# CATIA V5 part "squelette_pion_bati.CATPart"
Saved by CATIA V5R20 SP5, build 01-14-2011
Part number: squelette_pion_bati
Publications: "hauteur", "diametre", "Plan.1", "Point.1", "Plan.2", "Point.2", "Droite.1"
Bounding box of the stored display mesh (mm): x 0 to 0, y 0 to 16.61, z 0 to 0
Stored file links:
  F:\iao\catia\projet iao\squelette_pion_bati.CATPart
  F:\iao\catia\projet iao\fhartmann.CATProduct
  F:\iao\catia\projet iao\squelette_bielle.CATPart
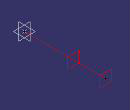
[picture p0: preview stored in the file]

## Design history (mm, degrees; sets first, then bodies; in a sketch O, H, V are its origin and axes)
Parameters
  hauteur = 16.61 mm {= External.bati_epaisseur_languette +External.bielle1_epaisseur}
  diametre = 10 mm {= External.bielle_diametre_int}
External parameters (linked from other documents)
  External.bati_epaisseur_languette = 10 mm
  External.bielle1_epaisseur = 6.61 mm
  External.bielle_diametre_int = 10 mm
  External.epaisseur = 6.61 mm
Set1
  Plane1: type Offset, RefPlane zx-plane, Offset 0
  Point1: type OnPlane, Support Plane1, H 0, V 0, Direction (-1, 0, 0)
  Plane2: type Offset, RefPlane Plane1, Offset 16.61 {= hauteur}
  Point2: type OnPlane, Support Plane2, H 0, V 0, Direction (-1, 0, 0)
  Line1: type PtPt, FirstPoint Point1, SecondPoint Point2
  Plane3: type Offset, RefPlane Plane2, Offset 6.61 {= External.epaisseur}, reversed
Body1 (main body)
